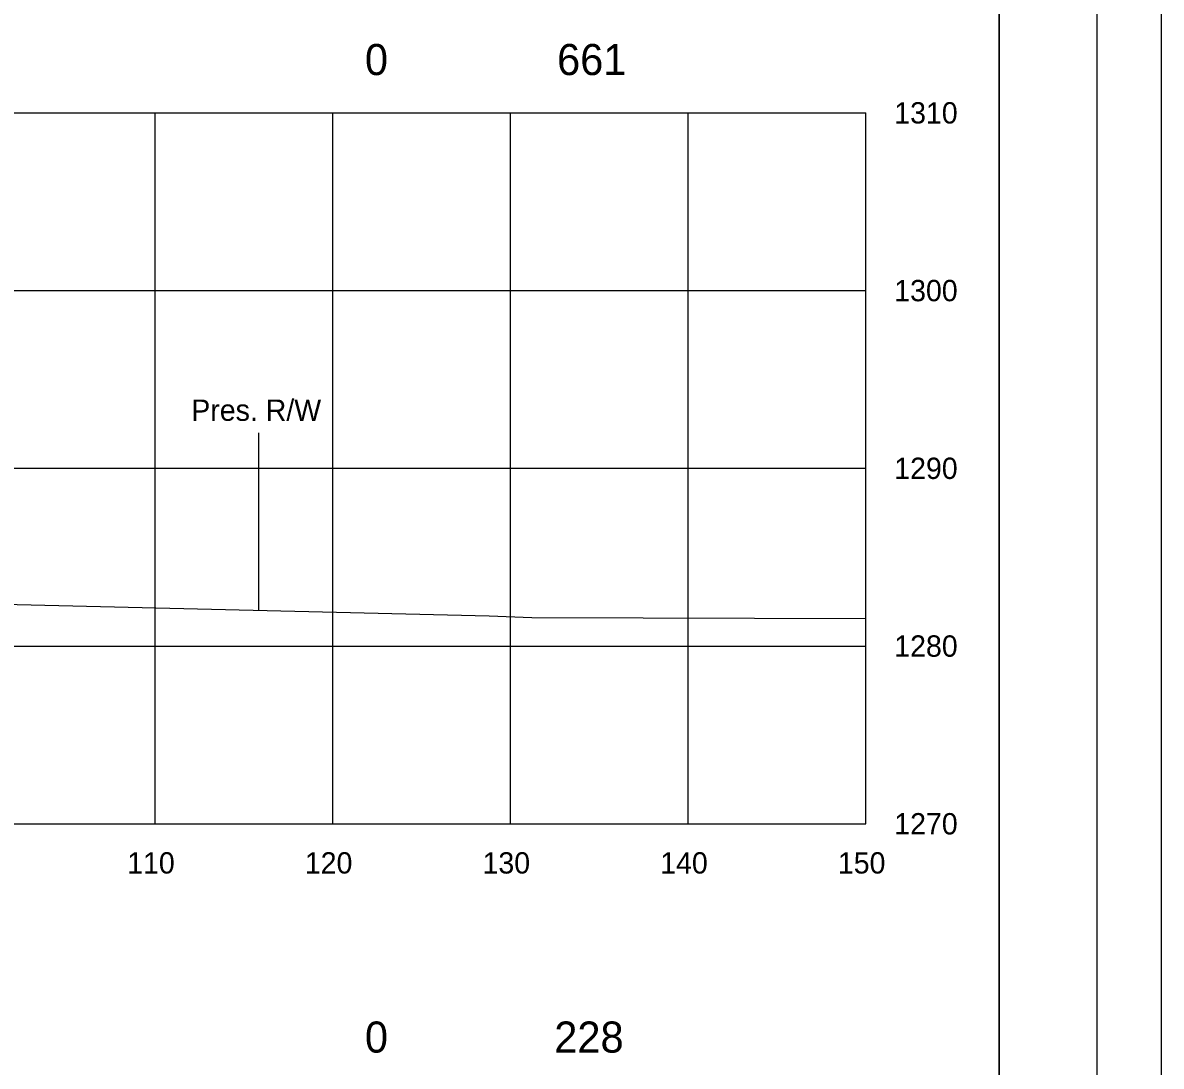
# Model space of a CAD drawing. Extents: x 2148105 to 2149976, y 144169 to 149705.
# Drawn here: x 2148515.9 to 2148579.9, y 144793.3 to 144852 of the extents above; entities that cross this region are included whole.
import ezdxf

# ---------------------------------------------------------------- set-up
doc = ezdxf.new("R2010")
doc.units = 0
for name, color, linetype in [('PH1a-PR-ServRd', 7, 'Continuous'), ('PR_Align_Ramp_A', 7, 'Continuous'), ('PR_Align_Ramp_E', 7, 'Continuous'), ('PR_Align_Ramp_J', 7, 'Continuous'), ('PR_Storm_Conc_Box_PH1B', 7, 'Continuous'), ('PR_Storm_Conc_Pipe_PH1B', 7, 'Continuous'), ('PR_Storm_Inlet_CICI_PH1B', 7, 'Continuous'), ('PR_Storm_MH_PH1A', 7, 'Continuous'), ('PR_Storm_MH_PH1B', 7, 'Continuous'), ('PR_Storm_Standard_Median_Drain_PH1B', 7, 'Continuous')]:
    doc.layers.add(name, color=color, linetype=linetype)

msp = doc.modelspace()

# ---------------------------------------------------------------- linework, layer by layer
at = {"layer": 'PH1a-PR-ServRd'}
msp.add_lwpolyline([(2148570.822, 144681.906), (2148255.822, 144681.906), (2148255.822, 144891.906), (2148570.822, 144891.906)], close=True, dxfattribs=at)
at = {"layer": 'PR_Align_Ramp_E'}
msp.add_lwpolyline([(2148219.947, 144905.156), (2148579.947, 144905.156), (2148579.947, 144665.156), (2148219.947, 144665.156)], close=True, dxfattribs=at)
at = {"layer": 'PR_Align_Ramp_J'}
msp.add_lwpolyline([(2148236.322, 144896.906), (2148576.322, 144896.906), (2148576.322, 144676.906), (2148236.322, 144676.906)], close=True, dxfattribs=at)
at = {"layer": 'PR_Storm_Conc_Box_PH1B'}
for p, q in [((2148263.322, 144846.906), (2148563.322, 144846.906)), ((2148523.322, 144806.906), (2148523.322, 144846.906)), ((2148533.322, 144806.906), (2148533.322, 144846.906)), ((2148543.322, 144806.906), (2148543.322, 144846.906)), ((2148553.322, 144806.906), (2148553.322, 144846.906)), ((2148563.322, 144806.906), (2148563.322, 144846.906)), ((2148263.322, 144836.906), (2148563.322, 144836.906)), ((2148263.322, 144826.906), (2148563.322, 144826.906)), ((2148263.322, 144816.906), (2148563.322, 144816.906)), ((2148263.322, 144806.906), (2148563.322, 144806.906))]:
    msp.add_line(p, q, dxfattribs=at)
at = {"layer": 'PR_Storm_Conc_Pipe_PH1B'}
msp.add_lwpolyline([(2148255.822, 144681.906), (2148570.822, 144681.906), (2148570.822, 144891.906), (2148255.822, 144891.906)], close=True, dxfattribs=at)
msp.add_lwpolyline([(2148255.822, 144681.906), (2148570.822, 144681.906), (2148570.822, 144891.906), (2148255.822, 144891.906)], close=True, dxfattribs=at)
at = {"layer": 'PR_Storm_Inlet_CICI_PH1B'}
msp.add_lwpolyline([(2148425.33, 144820.815), (2148431.399, 144820.76), (2148434.495, 144820.711), (2148447.036, 144820.543), (2148456.241, 144820.392), (2148462.685, 144820.192), (2148476.492, 144819.77), (2148478.757, 144819.82), (2148487.781, 144819.752), (2148499.401, 144819.502), (2148515.554, 144819.237), (2148542.124, 144818.6), (2148544.526, 144818.507), (2148563.322, 144818.454)], dxfattribs=at)
at = {"layer": 'PR_Storm_MH_PH1A'}
msp.add_line((2148529.158, 144818.911), (2148529.158, 144828.911), dxfattribs=at)
at = {"layer": 'PR_Storm_Standard_Median_Drain_PH1B'}
for p, q in [((2148563.322, 144806.906), (2148563.322, 144846.906)), ((2148263.322, 144806.906), (2148563.322, 144806.906))]:
    msp.add_line(p, q, dxfattribs=at)

# ---------------------------------------------------------------- texts
at = {"layer": 'PR_Align_Ramp_A'}
for s, p in [('0', (2148535.131, 144849.031)), ('661', (2148545.945, 144849.031)), ('0', (2148535.131, 144794.031)), ('228', (2148545.787, 144794.031))]:
    msp.add_text(s, height=1.75, dxfattribs=at).set_placement(p)
at = {"layer": 'PR_Storm_MH_PH1A'}
msp.add_text('Pres. R/W', height=1.2, rotation=360, dxfattribs=at).set_placement((2148525.358, 144829.577))
at = {"layer": 'PR_Storm_MH_PH1B'}
for s, p in [('1310', (2148564.922, 144846.306)), ('1300', (2148564.922, 144836.306)), ('1290', (2148564.922, 144826.306)), ('1280', (2148564.922, 144816.306)), ('1270', (2148564.922, 144806.306)), ('110', (2148521.749, 144804.106)), ('120', (2148531.749, 144804.106)), ('130', (2148541.749, 144804.106)), ('140', (2148551.749, 144804.106)), ('150', (2148561.749, 144804.106))]:
    msp.add_text(s, height=1.2, dxfattribs=at).set_placement(p)

doc.saveas('drawing.dxf')
